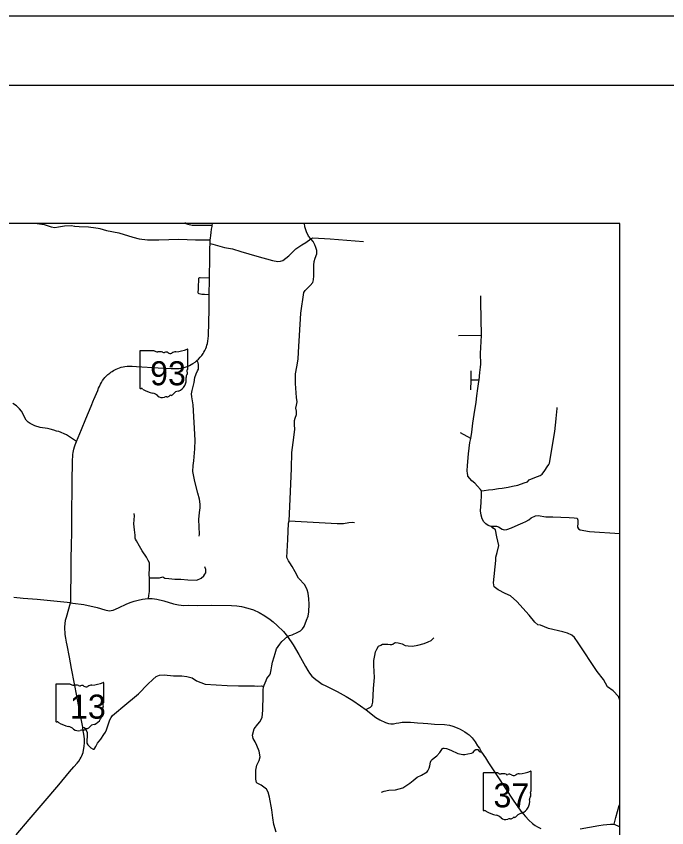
# Model space of a CAD drawing. Extents: x 2025369 to 2161369, y 549489 to 637489.
# Drawn here: x 2074950 to 2093780, y 613987 to 637489 of the extents above; entities that cross this region are included whole.
import ezdxf

# ---------------------------------------------------------------- set-up
doc = ezdxf.new("R2010")
doc.units = 0
for name, color, linetype in [('GM_X_County_Road', 7, 'Continuous'), ('GM_X_State_Route', 7, 'Continuous'), ('GM_X_State_Shield', 7, 'Continuous'), ('GM_X_Township_Road', 7, 'Continuous'), ('GM_X_Township_Subdivision', 7, 'Continuous'), ('SH_Border', 7, 'Continuous'), ('SH_Cut_Line', 7, 'Continuous'), ('SH_Text', 7, 'Continuous')]:
    doc.layers.add(name, color=color, linetype=linetype)

msp = doc.modelspace()

# ---------------------------------------------------------------- linework, layer by layer
at = {"layer": 'GM_X_County_Road'}
for points in [[(2075553, 631489), (2075754, 631459), (2075961, 631390), (2076067, 631372), (2076171, 631388), (2076348, 631417), (2076548, 631425), (2076639, 631414)], [(2076639, 631414), (2076648, 631413), (2076775, 631398), (2077045, 631389), (2077255, 631359), (2077319, 631350), (2077374, 631343), (2077567, 631283), (2077918, 631220), (2078326, 631087), (2078505, 631041), (2078753, 631013), (2079075, 631018), (2079655, 631030), (2080137, 631014), (2080568, 631018)], [(2088414, 623742), (2088392, 623783), (2088306, 623875), (2088220, 623967), (2088134, 624033), (2088079, 624106), (2088025, 624167), (2088019, 624195), (2088009, 624247), (2087999, 624328), (2088010, 624479), (2088044, 624813), (2088084, 625146), (2088104, 625263), (2088135, 625444), (2088167, 625709), (2088201, 625951), (2088261, 626317), (2088287, 626496), (2088314, 626709), (2088343, 626910), (2088347, 626946), (2088371, 627175), (2088393, 627326), (2088395, 627414), (2088388, 627719), (2088420, 628243), (2088403, 629216), (2088401, 629389)], [(2092420, 617685), (2092381, 617789), (2092230, 617954), (2092068, 618066), (2091946, 618278), (2091767, 618517), (2091218, 619347), (2091108, 619494), (2091036, 619563), (2090903, 619624), (2090772, 619659), (2090359, 619761), (2090127, 619852), (2090045, 619865), (2089957, 619945), (2089797, 620141), (2089437, 620543), (2089260, 620699), (2089101, 620774), (2088903, 620878), (2088783, 620960), (2088763, 621077), (2088828, 621731), (2088834, 621823), (2088875, 621955), (2088923, 622162), (2088864, 622410), (2088818, 622611), (2088754, 622666), (2088702, 622710), (2088608, 622744), (2088547, 622787), (2088488, 622850), (2088434, 622930), (2088412, 623044), (2088391, 623165), (2088410, 623411), (2088422, 623621), (2088422, 623714), (2088414, 623742)], [(2092257, 614093), (2092307, 614282), (2092407, 614628), (2092420, 614669)]]:
    msp.add_lwpolyline(points, dxfattribs=at)
at = {"layer": 'GM_X_State_Route'}
for points in [[(2080568, 631018), (2080572, 631065), (2080579, 631136), (2080590, 631227), (2080603, 631320), (2080617, 631399), (2080623, 631434), (2080631, 631478), (2080634, 631489)], [(2080556, 630762), (2080562, 630912), (2080566, 630993), (2080568, 631018)], [(2080524, 628554), (2080525, 628594), (2080530, 629021), (2080538, 629421), (2080545, 629864), (2080544, 629912), (2080554, 630497), (2080555, 630746), (2080556, 630762)], [(2077199, 626392), (2077308, 626655), (2077335, 626717), (2077360, 626771), (2077390, 626835), (2077416, 626883), (2077449, 626938), (2077484, 626985), (2077515, 627023), (2077581, 627092), (2077601, 627111), (2077630, 627136), (2077656, 627157), (2077687, 627179), (2077726, 627205), (2077769, 627232), (2077807, 627252), (2077847, 627272), (2077894, 627291), (2077940, 627308), (2077990, 627323), (2078044, 627337), (2078091, 627344), (2078160, 627351), (2078218, 627355), (2078305, 627354), (2078429, 627348), (2079059, 627310), (2079439, 627287), (2079511, 627284), (2079558, 627283), (2079604, 627285), (2079668, 627290), (2079739, 627302), (2079809, 627318), (2079894, 627346), (2079967, 627377), (2080061, 627428), (2080125, 627472), (2080178, 627516), (2080225, 627557), (2080277, 627613), (2080318, 627663), (2080342, 627696), (2080358, 627719), (2080380, 627758), (2080407, 627806), (2080436, 627867), (2080456, 627918), (2080471, 627962), (2080484, 628014), (2080498, 628078), (2080508, 628157), (2080514, 628233), (2080517, 628311), (2080524, 628554)], [(2076523, 620497), (2076526, 620533), (2076533, 620951), (2076536, 621143), (2076540, 621338), (2076544, 621771), (2076549, 622174), (2076555, 622536), (2076559, 622903), (2076563, 623272), (2076568, 623679), (2076573, 624073), (2076580, 624525), (2076581, 624644), (2076584, 624736), (2076588, 624793), (2076596, 624859), (2076615, 624953), (2076635, 625015), (2076658, 625080), (2076695, 625176), (2076839, 625520), (2076967, 625829), (2077121, 626200), (2077189, 626366), (2077199, 626392)], [(2076523, 620497), (2075554, 620599), (2075146, 620629), (2074879, 620652)], [(2074949, 613783), (2075328, 614229), (2075728, 614703), (2076179, 615235), (2076494, 615607), (2076618, 615751), (2076712, 615862), (2076758, 615918), (2076805, 615980), (2076834, 616028), (2076852, 616068), (2076871, 616114), (2076887, 616165), (2076901, 616230), (2076910, 616284), (2076917, 616350), (2076923, 616449), (2076925, 616503), (2076923, 616565), (2076917, 616634), (2076909, 616694), (2076892, 616797), (2076873, 616901), (2076836, 617093), (2076771, 617442), (2076700, 617806), (2076637, 618153), (2076553, 618596), (2076490, 618927), (2076425, 619273), (2076425, 619277), (2076408, 619363), (2076385, 619478), (2076369, 619586), (2076362, 619652), (2076359, 619730), (2076359, 619808), (2076365, 619895), (2076380, 619995), (2076401, 620090), (2076523, 620497)], [(2076523, 620497), (2076588, 620490), (2076905, 620455), (2077288, 620364), (2077515, 620296), (2077642, 620269), (2077753, 620291), (2077909, 620357), (2078147, 620469), (2078273, 620521), (2078366, 620547), (2078484, 620578), (2078603, 620603), (2078680, 620616), (2078779, 620623), (2078881, 620629), (2079020, 620610), (2079218, 620557), (2079506, 620472), (2079645, 620439), (2079802, 620424), (2079930, 620429), (2080192, 620424), (2080611, 620429), (2081184, 620426), (2081339, 620416), (2081467, 620395), (2081655, 620348), (2081820, 620294), (2081983, 620218), (2082144, 620127), (2082303, 620015), (2082386, 619951), (2082507, 619846), (2082687, 619673), (2082800, 619525), (2082962, 619281), (2083127, 619000), (2083319, 618658), (2083391, 618546), (2083436, 618460), (2083510, 618381), (2083623, 618280), (2083685, 618234), (2083804, 618149), (2083913, 618101), (2084240, 617933), (2084498, 617787), (2084690, 617670), (2084918, 617518), (2085079, 617400), (2085358, 617183), (2085473, 617108), (2085635, 617031), (2085729, 617008), (2085791, 616997), (2085868, 617001), (2085947, 617014), (2086028, 617029), (2086118, 617044), (2086225, 617046), (2086361, 617042), (2086466, 617036), (2086569, 617023), (2086729, 617014), (2086868, 617004), (2087055, 616986), (2087343, 616974), (2087487, 616956), (2087587, 616931), (2087716, 616884), (2087799, 616846), (2087932, 616766), (2088007, 616719), (2088056, 616682), (2088144, 616595), (2088233, 616475), (2088306, 616362), (2088361, 616288), (2088419, 616180), (2088530, 616016), (2088616, 615868), (2088867, 615492), (2089334, 614788), (2089560, 614463), (2089691, 614315), (2089785, 614205), (2089895, 614108), (2089973, 614054), (2090034, 614014), (2090132, 613963)], [(2091271, 613957), (2091814, 614053)], [(2091814, 614053), (2091935, 614074), (2092147, 614091), (2092257, 614093), (2092407, 614019), (2092420, 614010)]]:
    msp.add_lwpolyline(points, dxfattribs=at)
at = {"layer": 'GM_X_State_Shield'}
for p, q in [((2078525, 627783), (2078525, 626726)), ((2078947, 627801), (2078539, 627801)), ((2079918, 627275), (2079918, 627827)), ((2079917, 627275), (2079918, 627275)), ((2076092, 618129), (2076092, 617073)), ((2076514, 618148), (2076106, 618148)), ((2077484, 617621), (2077484, 618174)), ((2077484, 617621), (2077484, 617621)), ((2088465, 615560), (2088465, 614503)), ((2088886, 615578), (2088479, 615578)), ((2089857, 615052), (2089857, 615604)), ((2089857, 615052), (2089857, 615052))]:
    msp.add_line(p, q, dxfattribs=at)
for centre, radius, start, end in [((2078541, 627785), 16.1, 98.1301, 188.1301), ((2079044, 627924), 156, 231.6195, 271.1119), ((2079096, 627208), 562, 80.4867, 94.9883), ((2079223, 627791), 45.1, 219.7921, 297.1024), ((2079290, 627669), 93.8, 54.4667, 119.1411), ((2079610, 627479), 297, 97.3462, 120.7689), ((2079422, 629242), 1476, 275.8445, 288.9065), ((2079902, 627830), 15.5, 351.8621, 97.738), ((2079411, 627836), 113, 233.8562, 294.8282), ((2079973, 627043), 105, 136.8065, 186.9296), ((2079914, 627234), 24, 107.944, 210.337), ((2079761, 627164), 144, 340.033, 23.6496), ((2079901, 627273), 16.6, 289.6038, 7.7341), ((2079504, 626973), 369, 292.3089, 8.9858), ((2078541, 626724), 16.3, 171.9584, 258.3066), ((2078544, 626832), 124, 267.339, 280.6039), ((2078569, 626665), 44.8, 29.7484, 93.2717), ((2079135, 627615), 1066, 240.4129, 257.1985), ((2079660, 626430), 202, 94.4031, 142.5768), ((2078817, 626252), 334, 47.1842, 75.836), ((2079178, 626660), 212, 230.7004, 286.2918), ((2079300, 626295), 174, 85.6951, 111.2099), ((2079315, 626581), 113, 268.777, 315.5493), ((2079417, 626479), 31.8, 65.7517, 132.6484), ((2079404, 626624), 119, 282.8732, 323.2771), ((2076108, 618132), 16.1, 98.1301, 188.1301), ((2076611, 618270), 156, 231.6195, 271.1119), ((2076988, 619588), 1476, 275.8445, 288.9065), ((2077469, 618176), 15.5, 351.8621, 97.738), ((2076663, 617554), 562, 80.4867, 94.9883), ((2076790, 618137), 45.1, 219.7921, 297.1024), ((2076856, 618015), 93.8, 54.4667, 119.1411), ((2076977, 618183), 113, 233.8562, 294.8282), ((2077177, 617825), 297, 97.3462, 120.7689), ((2077540, 617390), 105, 136.8065, 186.9296), ((2077481, 617581), 24, 107.944, 210.337), ((2077328, 617511), 144, 340.033, 23.6496), ((2077468, 617619), 16.6, 289.6038, 7.7341), ((2077071, 617319), 369, 292.3089, 8.9858), ((2076108, 617071), 16.3, 171.9584, 258.3066), ((2076111, 617179), 124, 267.339, 280.6039), ((2076136, 617012), 44.8, 29.7484, 93.2717), ((2076701, 617961), 1066, 240.4129, 257.1985), ((2077227, 616776), 202, 94.4031, 142.5768), ((2076384, 616598), 334, 47.1842, 75.836), ((2076744, 617007), 212, 230.7004, 286.2918), ((2076867, 616641), 174, 85.6951, 111.2099), ((2076882, 616928), 113, 268.777, 315.5493), ((2076984, 616825), 31.8, 65.7517, 132.6484), ((2076971, 616970), 119, 282.8732, 323.2771), ((2088481, 615562), 16.1, 98.1301, 188.1301), ((2088983, 615701), 156, 231.6195, 271.1119), ((2089035, 614985), 562, 80.4867, 94.9883), ((2089163, 615568), 45.1, 219.7921, 297.1024), ((2089229, 615445), 93.8, 54.4667, 119.1411), ((2089550, 615255), 297, 97.3462, 120.7689), ((2089361, 617019), 1476, 275.8445, 288.9065), ((2089842, 615607), 15.5, 351.8621, 97.738), ((2089350, 615613), 113, 233.8562, 294.8282), ((2089913, 614820), 105, 136.8065, 186.9296), ((2089854, 615011), 24, 107.944, 210.337), ((2089701, 614941), 144, 340.033, 23.6496), ((2089841, 615049), 16.6, 289.6038, 7.7341), ((2089444, 614750), 369, 292.3089, 8.9858), ((2088481, 614501), 16.3, 171.9584, 258.3066), ((2088484, 614609), 124, 267.339, 280.6039), ((2088509, 614442), 44.8, 29.7484, 93.2717), ((2089074, 615392), 1066, 240.4129, 257.1985), ((2089600, 614207), 202, 94.4031, 142.5768), ((2088756, 614029), 334, 47.1842, 75.836), ((2089117, 614437), 212, 230.7004, 286.2918), ((2089239, 614072), 174, 85.6951, 111.2099), ((2089255, 614358), 113, 268.777, 315.5493), ((2089357, 614256), 31.8, 65.7517, 132.6484), ((2089343, 614401), 119, 282.8732, 323.2771)]:
    msp.add_arc(centre, radius, start, end, dxfattribs=at)
at = {"layer": 'GM_X_Township_Road'}
for points in [[(2079832, 631512), (2079856, 631486), (2079920, 631471), (2080039, 631440), (2080274, 631441), (2080505, 631440), (2080623, 631434)], [(2083572, 630379), (2083572, 630386), (2083600, 630479), (2083650, 630611), (2083650, 630707), (2083626, 630788), (2083593, 630868), (2083543, 630966), (2083474, 631047), (2083406, 631124), (2083349, 631241), (2083305, 631394), (2083296, 631489)], [(2083474, 631047), (2083474, 631047), (2083536, 631072), (2084036, 631041), (2085006, 630967)], [(2080562, 630912), (2080641, 630891), (2080982, 630793), (2081206, 630752), (2081455, 630673), (2081912, 630540), (2082367, 630420), (2082518, 630384), (2082601, 630397), (2082670, 630416), (2082844, 630549), (2083046, 630751), (2083221, 630865), (2083334, 630933), (2083474, 631047)], [(2082470, 613857), (2082410, 614084), (2082378, 614270), (2082348, 614506), (2082283, 614874), (2082242, 615016), (2082194, 615105), (2082121, 615161), (2082044, 615220), (2081923, 615275), (2081907, 615296), (2081885, 615392), (2081890, 615655), (2081917, 615803), (2081986, 615936), (2082012, 616043), (2081985, 616202), (2081910, 616366), (2081865, 616475), (2081807, 616575), (2081793, 616673), (2081840, 616855), (2081939, 616989), (2081998, 617050), (2082066, 617180), (2082086, 617390), (2082093, 617828), (2082098, 617986), (2082108, 618062), (2082131, 618115), (2082189, 618249), (2082203, 618306), (2082241, 618355), (2082287, 618416), (2082309, 618464), (2082327, 618563), (2082344, 618677), (2082365, 618778), (2082412, 618940), (2082445, 619033), (2082487, 619168), (2082577, 619306), (2082635, 619377), (2082800, 619525), (2082857, 619551), (2082941, 619571), (2083103, 619647), (2083175, 619693), (2083236, 619745), (2083280, 619818), (2083352, 620002), (2083402, 620117), (2083416, 620244), (2083427, 620463), (2083418, 620617), (2083404, 620777), (2083368, 620881), (2083305, 621026), (2083116, 621220), (2083023, 621402), (2082936, 621550), (2082868, 621658), (2082828, 621713), (2082781, 621812), (2082814, 622340), (2082835, 622805), (2082853, 622871), (2082879, 623502), (2082915, 624395), (2082930, 624856), (2082985, 625287), (2083010, 625529), (2083008, 625654), (2083003, 625784), (2083024, 625850), (2083058, 625953), (2083058, 626054), (2083046, 626142), (2083064, 626226), (2083080, 626322), (2083064, 626450), (2083038, 626854), (2083036, 627137), (2083072, 627332), (2083111, 627562), (2083119, 627758), (2083187, 628887), (2083279, 629487), (2083314, 629550), (2083458, 629691), (2083532, 629781), (2083557, 629858), (2083567, 629975), (2083565, 630194), (2083567, 630288), (2083572, 630379)], [(2080247, 622430), (2080251, 622486), (2080233, 622915), (2080257, 623115), (2080275, 623253), (2080278, 623363), (2080254, 623501), (2080202, 623677), (2080119, 624019), (2080064, 624302), (2080075, 624482), (2080092, 624617), (2080121, 624962), (2080127, 625209), (2080071, 626232), (2080031, 626463), (2080027, 626552), (2080043, 626655), (2080096, 626885), (2080122, 627030), (2080158, 627131), (2080195, 627216), (2080222, 627273), (2080228, 627338), (2080228, 627400), (2080214, 627455), (2080194, 627493), (2080178, 627516)], [(2076695, 625176), (2076695, 625176), (2076404, 625369), (2076179, 625460), (2076116, 625475), (2076037, 625502), (2075931, 625527), (2075855, 625549), (2075643, 625581), (2075489, 625625), (2075350, 625694), (2075295, 625730), (2075241, 625793), (2075203, 625855), (2075155, 625968), (2075103, 626051), (2075045, 626123), (2074953, 626208), (2074852, 626274)], [(2090574, 625833), (2090575, 625838), (2090605, 626128), (2090610, 626162)], [(2088414, 623742), (2088492, 623752), (2088621, 623774), (2088741, 623786), (2088914, 623810), (2089018, 623818), (2089193, 623847), (2089313, 623875), (2089472, 623910), (2089657, 623974), (2089750, 624010), (2089795, 624060), (2089912, 624115), (2090037, 624157), (2090118, 624188), (2090175, 624223), (2090247, 624333), (2090317, 624444), (2090370, 624509), (2090388, 624549), (2090536, 625462), (2090574, 625833)], [(2078803, 621227), (2078796, 621310), (2078809, 621518), (2078812, 621610), (2078804, 621656), (2078773, 621727), (2078720, 621824), (2078599, 622003), (2078514, 622144), (2078428, 622298), (2078406, 622341), (2078392, 622375), (2078388, 622422), (2078389, 622459), (2078369, 622615), (2078360, 622700), (2078357, 622785), (2078362, 622901), (2078375, 623025), (2078363, 623092)], [(2082853, 622871), (2084242, 622803), (2084424, 622794), (2084578, 622823), (2084675, 622837), (2084743, 622828)], [(2088754, 622666), (2088710, 622722), (2088792, 622718), (2088854, 622717), (2088912, 622706), (2089014, 622638), (2089070, 622611), (2089154, 622621), (2089287, 622676), (2089483, 622763), (2089614, 622814), (2089701, 622853), (2089786, 622901), (2089859, 622962), (2089976, 623020), (2090059, 623026), (2090278, 622992), (2090486, 622994), (2090710, 622985), (2090956, 622973), (2091104, 622966), (2091184, 622950), (2091203, 622898), (2091203, 622815), (2091200, 622693), (2091228, 622648), (2091269, 622612), (2091548, 622568), (2092420, 622505)], [(2078779, 620623), (2078788, 620713), (2078803, 620831), (2078803, 620996), (2078809, 621101), (2078812, 621169), (2078803, 621227), (2078915, 621229), (2079093, 621223), (2079195, 621251), (2079254, 621218), (2079370, 621201), (2079543, 621188), (2079710, 621182), (2079917, 621170), (2080182, 621161), (2080301, 621219), (2080380, 621286), (2080409, 621329), (2080438, 621369), (2080440, 621420), (2080442, 621467), (2080408, 621547)], [(2085079, 617400), (2085107, 617436), (2085202, 617480), (2085241, 617515), (2085253, 617547), (2085269, 617628), (2085289, 618021), (2085318, 618336), (2085298, 618687), (2085301, 618828), (2085332, 618979), (2085350, 619079), (2085387, 619161), (2085437, 619244), (2085500, 619277), (2085550, 619302), (2085625, 619308), (2085705, 619307), (2085774, 619295), (2085818, 619295), (2085847, 619306), (2085895, 619343), (2085930, 619355), (2086007, 619347), (2086125, 619315), (2086206, 619269), (2086290, 619251), (2086424, 619249), (2086574, 619274), (2086757, 619322), (2086878, 619372), (2086959, 619409), (2087037, 619483)], [(2076873, 616901), (2076912, 616886), (2076940, 616863), (2076962, 616826), (2077001, 616752), (2077000, 616646), (2076989, 616503), (2076992, 616437), (2077024, 616392), (2077105, 616306), (2077174, 616264), (2077201, 616266), (2077227, 616289), (2077250, 616342), (2077305, 616441), (2077395, 616552), (2077488, 616684), (2077535, 616755), (2077561, 616821), (2077590, 616907), (2077661, 617115), (2077694, 617177), (2077736, 617239), (2077851, 617334), (2078034, 617491), (2078489, 617865), (2078757, 618148), (2078904, 618284), (2079005, 618364), (2079098, 618402), (2079236, 618413), (2079504, 618388), (2079742, 618389), (2079892, 618367), (2080041, 618325), (2080167, 618241), (2080418, 618150), (2081052, 618108), (2081385, 618094), (2081502, 618094), (2081664, 618101), (2081842, 618098), (2081945, 618091), (2082052, 618096), (2082081, 618087), (2082108, 618062)], [(2085520, 615016), (2085596, 615051), (2085736, 615074), (2085927, 615086), (2086139, 615141), (2086345, 615283), (2086435, 615351), (2086560, 615450), (2086676, 615509), (2086843, 615603), (2086867, 615631), (2086906, 615715), (2086919, 615781), (2086939, 615885), (2086958, 615933), (2086989, 615966), (2087046, 616013), (2087124, 616072), (2087211, 616168), (2087285, 616279), (2087311, 616292), (2087337, 616292), (2087400, 616282), (2087528, 616233), (2087737, 616142), (2087832, 616115), (2087878, 616109), (2087939, 616111), (2088024, 616126), (2088124, 616143), (2088178, 616171), (2088200, 616199), (2088223, 616230), (2088249, 616250), (2088278, 616258), (2088311, 616254), (2088349, 616210), (2088377, 616182), (2088419, 616180)]]:
    msp.add_lwpolyline(points, dxfattribs=at)
at = {"layer": 'GM_X_Township_Subdivision'}
for points in [[(2080225, 629458), (2080215, 629481), (2080220, 629509), (2080223, 629572), (2080228, 629644), (2080234, 629878), (2080238, 629903), (2080249, 629913), (2080263, 629921), (2080275, 629924)], [(2080275, 629924), (2080544, 629912)], [(2080538, 629421), (2080404, 629427), (2080320, 629434), (2080248, 629449), (2080225, 629458)], [(2088420, 628243), (2087751, 628229)], [(2088110, 626666), (2088123, 626948), (2088123, 627217)], [(2088347, 626946), (2088123, 626948)], [(2088104, 625263), (2087808, 625427)]]:
    msp.add_lwpolyline(points, dxfattribs=at)
at = {"layer": 'SH_Border'}
msp.add_lwpolyline([(2033369, 635489), (2159369, 635489), (2159369, 551489), (2033369, 551489)], close=True, dxfattribs=at)
at = {"layer": 'SH_Cut_Line'}
msp.add_lwpolyline([(2025369, 549489), (2161369, 549489), (2161369, 637489), (2025369, 637489)], close=True, dxfattribs=at)
at = {"layer": 'SH_Text'}
msp.add_line((2092420, 631489), (2037369, 631489), dxfattribs=at)
msp.add_lwpolyline([(2037369, 631489), (2037369, 571561), (2092420, 571561), (2092420, 631489)], dxfattribs=at)

# ---------------------------------------------------------------- texts
at = {"layer": 'GM_X_State_Shield'}
for s, p in [('93', (2078826, 626801)), ('13', (2076507, 617147)), ('37', (2088765, 614578))]:
    msp.add_text(s, height=696.1, dxfattribs=at).set_placement(p)

doc.saveas('drawing.dxf')
